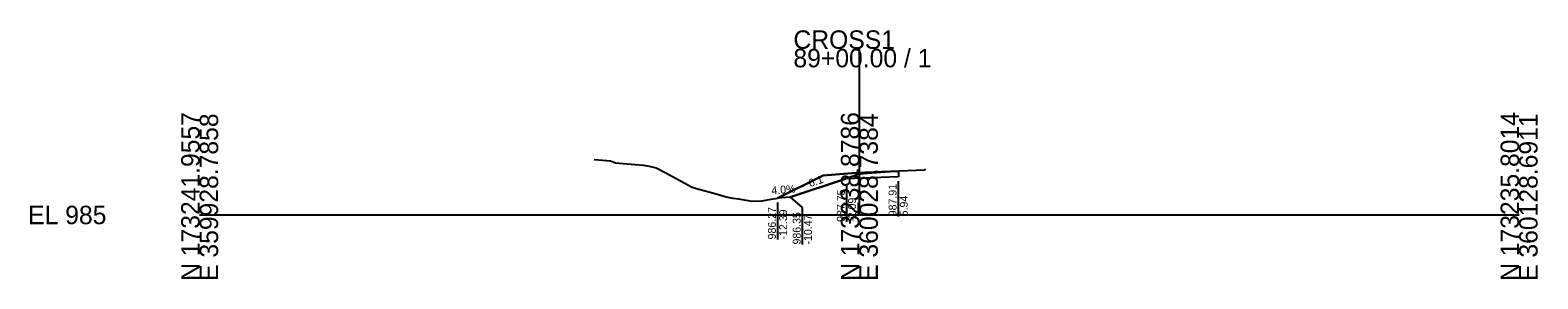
# Model space of a CAD drawing. Extents: x -26 to 1403, y -10 to 11027.
# Drawn here: x -25.7 to 202.8, y 3990.3 to 4028 of the extents above; entities that cross this region are included whole.
import ezdxf

# ---------------------------------------------------------------- set-up
doc = ezdxf.new("R2010")
doc.units = 0
for name, color, linetype in [('Default', 7, 'Continuous'), ('P_E_XS_Ground', 7, 'Continuous'), ('P_XS', 7, 'Continuous'), ('P_XS_EAR_CommonGrnd', 7, 'Continuous'), ('P_XS_Lane', 7, 'Continuous'), ('P_XS_Rock', 7, 'Continuous')]:
    doc.layers.add(name, color=color, linetype=linetype)

msp = doc.modelspace()

# ---------------------------------------------------------------- linework, layer by layer
at = {"layer": 'Default'}
for p, q in [((100, 4000), (100, 4025.2)), ((0, 4000), (100, 4000)), ((100, 4000), (200, 4000))]:
    msp.add_line(p, q, dxfattribs=at)
at = {"layer": 'P_E_XS_Ground'}
for p, q in [((59.82, 4008.4), (60.47, 4008.38)), ((60.47, 4008.38), (62.26, 4008.22)), ((62.26, 4008.22), (63.02, 4007.9)), ((63.02, 4007.9), (64.81, 4007.74)), ((64.81, 4007.74), (65.99, 4007.66)), ((65.99, 4007.66), (67.26, 4007.56)), ((67.26, 4007.56), (68.12, 4007.4)), ((68.12, 4007.4), (69.18, 4007.16)), ((69.18, 4007.16), (70.55, 4006.42)), ((70.55, 4006.42), (74.67, 4004.24)), ((99.5, 4006.39), (94.5, 4005.99)), ((109.94, 4006.81), (99.5, 4006.39)), ((109.94, 4006.95), (109.98, 4006.95)), ((109.94, 4006.95), (109.94, 4006.81)), ((74.67, 4004.24), (75.32, 4004)), ((75.32, 4004), (78.31, 4003.23)), ((94.5, 4005.99), (87.61, 4002.55)), ((78.31, 4003.23), (79.82, 4002.75)), ((79.82, 4002.75), (80.81, 4002.57)), ((80.81, 4002.57), (81.68, 4002.44)), ((81.68, 4002.44), (83.7, 4002.1)), ((83.7, 4002.1), (85.27, 4002.14)), ((85.27, 4002.14), (86.65, 4002.41)), ((86.65, 4002.41), (87.61, 4002.55))]:
    msp.add_line(p, q, dxfattribs=at)
at = {"layer": 'P_XS'}
for p, q in [((105.94, 4006.65), (99.94, 4006.17)), ((99.94, 4006.17), (97.91, 4005.49))]:
    msp.add_line(p, q, dxfattribs=at)
at = {"layer": 'P_XS_EAR_CommonGrnd'}
msp.add_lwpolyline([(105.94, 4005.81), (97.91, 4005.49), (89.53, 4002.7), (87.61, 4002.55), (94.5, 4005.99), (99.5, 4006.39), (105.94, 4006.65)], close=True, dxfattribs=at)
at = {"layer": 'P_XS_Lane'}
for p, q in [((105.94, 4006.65), (105.94, 4005.81)), ((89.53, 4002.7), (97.91, 4005.49)), ((105.94, 4005.81), (97.91, 4005.49)), ((89.53, 4002.7), (87.61, 4002.55))]:
    msp.add_line(p, q, dxfattribs=at)
at = {"layer": 'P_XS_Rock'}
for p, q in [((98.04, 4004.56), (98.04, 3998.96)), ((105.88, 4005.11), (105.88, 3999.79)), ((87.59, 4001.88), (87.59, 3996.29)), ((89.53, 4002.7), (91.35, 4001.11)), ((91.35, 4001.11), (91.35, 3995.52))]:
    msp.add_line(p, q, dxfattribs=at)

# ---------------------------------------------------------------- texts
at = {"layer": 'Default'}
for s, p in [('CROSS1', (90, 4025.2)), ('89+00.00 / 1', (90, 4022.4)), ('EL 985', (-26, 3998.6))]:
    msp.add_text(s, height=2.8, dxfattribs=at).set_placement(p)
for s, p in [('N 173241.9557', (0, 3990)), ('N 173238.8786', (100, 3990)), ('N 173235.8014', (200, 3990)), ('E 359928.7858', (2.8, 3990)), ('E 360028.7384', (102.8, 3990)), ('E 360128.6911', (202.8, 3990))]:
    msp.add_text(s, height=2.8, rotation=90, dxfattribs=at).set_placement(p)
at = {"layer": 'P_XS_Rock'}
for s, rotation, p in [('4.0%', 4.5739, (86.71, 4003.11)), ('6:1', 18.4349, (92.52, 4004.21)), ('987.91', 90, (105.63, 3999.8)), ('987.75', 90, (97.79, 3998.96)), ('-2.09', 90, (99.49, 3998.96)), ('5.94', 90, (107.33, 3999.8)), ('986.27', 90, (87.34, 3996.29)), ('-12.39', 90, (89.04, 3996.29)), ('986.35', 90, (91.1, 3995.52)), ('-10.47', 90, (92.8, 3995.52))]:
    msp.add_text(s, height=1.2, rotation=rotation, dxfattribs=at).set_placement(p)

doc.saveas('drawing.dxf')
